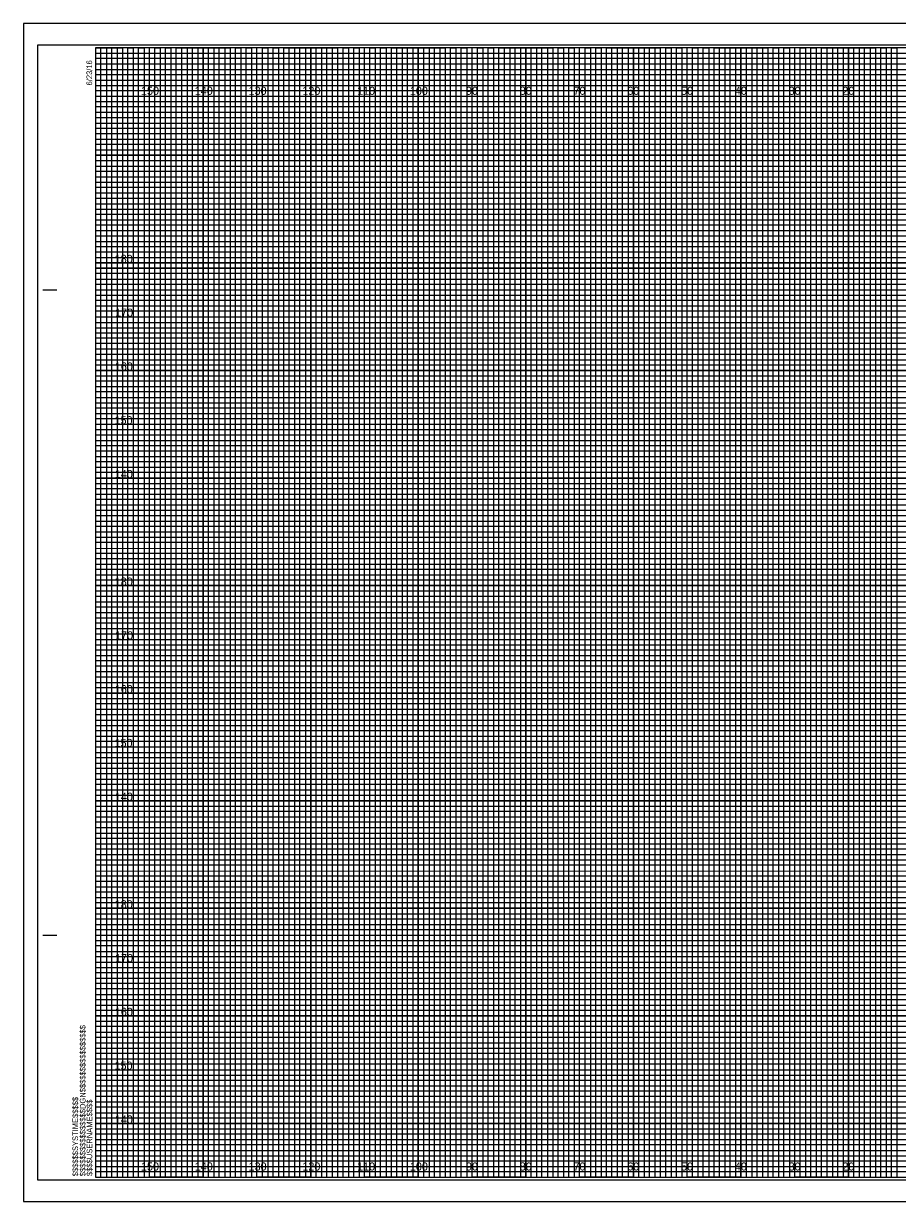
# Model space of a CAD drawing. Extents: x -13 to 323, y -5 to 4834.
# Drawn here: x -13.4 to 149.1, y 435.5 to 654.5 of the extents above; entities that cross this region are included whole.
import ezdxf

# ---------------------------------------------------------------- set-up
doc = ezdxf.new("R2010")
doc.units = 0
for name, color, linetype in [('Exist Cross Section Cell', 7, 'Continuous'), ('Exist XS Center Line Elevation Label', 7, 'Continuous'), ('Exist XS Ground Line', 7, 'Continuous'), ('Prop CMT Pvmt Course 1', 7, 'Continuous'), ('Prop CMT Pvmt Course 2', 7, 'Continuous'), ('Prop CMT Pvmt Course 3', 7, 'Continuous'), ('Prop CMT Pvmt Surface Shoulder', 7, 'Continuous'), ('Prop CMT Shld Paved Course 1', 7, 'Continuous'), ('Prop CMT Shld Paved Course 2', 7, 'Continuous'), ('Prop CMT Shld Paved Course 3', 7, 'Continuous'), ('Prop CMT Slope Grass', 7, 'Continuous')]:
    doc.layers.add(name, color=color, linetype=linetype)

msp = doc.modelspace()

# ---------------------------------------------------------------- linework, layer by layer
at = {"layer": 'Exist XS Center Line Elevation Label'}
for points in [[(0, 650), (5, 650), (5, 440), (15, 440), (15, 650), (25, 650), (25, 440), (35, 440), (35, 650), (45, 650), (45, 440), (55, 440), (55, 650), (65, 650), (65, 440), (75, 440), (75, 650), (85, 650), (85, 440), (95, 440), (95, 650), (105, 650), (105, 440), (115, 440), (115, 650), (125, 650), (125, 440), (135, 440), (135, 650), (145, 650), (145, 440), (155, 440)], [(0, 645), (275, 645)], [(0, 625), (320, 625), (320, 635), (0, 635)], [(0, 605), (320, 605), (320, 615), (0, 615)], [(0, 585), (320, 585), (320, 595), (0, 595)], [(0, 565), (320, 565), (320, 575), (0, 575)], [(0, 545), (320, 545), (320, 555), (0, 555)], [(0, 525), (320, 525), (320, 535), (0, 535)], [(0, 505), (320, 505), (320, 515), (0, 515)], [(0, 485), (320, 485), (320, 495), (0, 495)], [(0, 465), (320, 465), (320, 475), (0, 475)], [(0, 445), (320, 445), (320, 455), (0, 455)]]:
    msp.add_lwpolyline(points, dxfattribs=at)
at = {"layer": 'Exist XS Ground Line'}
for p, q in [((10, 650), (0, 650)), ((10, 440), (10, 650)), ((30, 650), (20, 650)), ((20, 650), (20, 440)), ((30, 440), (30, 650)), ((50, 650), (40, 650)), ((40, 650), (40, 440)), ((50, 440), (50, 650)), ((70, 650), (60, 650)), ((60, 650), (60, 440)), ((70, 440), (70, 650)), ((90, 650), (80, 650)), ((80, 650), (80, 440)), ((90, 440), (90, 650)), ((110, 650), (100, 650)), ((100, 650), (100, 440)), ((110, 440), (110, 650)), ((130, 650), (120, 650)), ((120, 650), (120, 440)), ((130, 440), (130, 650)), ((150, 650), (140, 650)), ((140, 650), (140, 440)), ((20, 440), (10, 440)), ((40, 440), (30, 440)), ((60, 440), (50, 440)), ((80, 440), (70, 440)), ((100, 440), (90, 440)), ((120, 440), (110, 440)), ((140, 440), (130, 440))]:
    msp.add_line(p, q, dxfattribs=at)
for points in [[(0, 640), (320, 640), (320, 630), (0, 630)], [(0, 620), (320, 620), (320, 610), (0, 610)], [(0, 600), (320, 600), (320, 590), (0, 590)], [(0, 580), (320, 580), (320, 570), (0, 570)], [(0, 560), (320, 560), (320, 550), (0, 550)], [(0, 540), (320, 540), (320, 530), (0, 530)], [(0, 520), (320, 520), (320, 510), (0, 510)], [(0, 500), (320, 500), (320, 490), (0, 490)], [(0, 480), (320, 480), (320, 470), (0, 470)], [(0, 460), (320, 460), (320, 450), (0, 450)]]:
    msp.add_lwpolyline(points, dxfattribs=at)
at = {"layer": 'Prop CMT Pvmt Course 1'}
for points in [[(0, 440), (1, 440), (1, 650), (2, 650), (2, 440)], [(2, 440), (3, 440), (3, 650), (4, 650), (4, 440)], [(5, 440), (6, 440), (6, 650), (7, 650), (7, 440)], [(7, 440), (8, 440), (8, 650), (9, 650), (9, 440)], [(10, 440), (11, 440), (11, 650), (12, 650), (12, 440)], [(12, 440), (13, 440), (13, 650), (14, 650), (14, 440)], [(15, 440), (16, 440), (16, 650), (17, 650), (17, 440)], [(17, 440), (18, 440), (18, 650), (19, 650), (19, 440)], [(20, 440), (21, 440), (21, 650), (22, 650), (22, 440)], [(22, 440), (23, 440), (23, 650), (24, 650), (24, 440)], [(25, 440), (26, 440), (26, 650), (27, 650), (27, 440)], [(27, 440), (28, 440), (28, 650), (29, 650), (29, 440)], [(30, 440), (31, 440), (31, 650), (32, 650), (32, 440)], [(32, 440), (33, 440), (33, 650), (34, 650), (34, 440)], [(35, 440), (36, 440), (36, 650), (37, 650), (37, 440)], [(37, 440), (38, 440), (38, 650), (39, 650), (39, 440)], [(40, 440), (41, 440), (41, 650), (42, 650), (42, 440)], [(42, 440), (43, 440), (43, 650), (44, 650), (44, 440)], [(45, 440), (46, 440), (46, 650), (47, 650), (47, 440)], [(47, 440), (48, 440), (48, 650), (49, 650), (49, 440)], [(50, 440), (51, 440), (51, 650), (52, 650), (52, 440)], [(52, 440), (53, 440), (53, 650), (54, 650), (54, 440)], [(55, 440), (56, 440), (56, 650), (57, 650), (57, 440)], [(57, 440), (58, 440), (58, 650), (59, 650), (59, 440)], [(60, 440), (61, 440), (61, 650), (62, 650), (62, 440)], [(62, 440), (63, 440), (63, 650), (64, 650), (64, 440)], [(65, 440), (66, 440), (66, 650), (67, 650), (67, 440)], [(67, 440), (68, 440), (68, 650), (69, 650), (69, 440)], [(70, 440), (71, 440), (71, 650), (72, 650), (72, 440)], [(72, 440), (73, 440), (73, 650), (74, 650), (74, 440)], [(75, 440), (76, 440), (76, 650), (77, 650), (77, 440)], [(77, 440), (78, 440), (78, 650), (79, 650), (79, 440)], [(80, 440), (81, 440), (81, 650), (82, 650), (82, 440)], [(82, 440), (83, 440), (83, 650), (84, 650), (84, 440)], [(85, 440), (86, 440), (86, 650), (87, 650), (87, 440)], [(87, 440), (88, 440), (88, 650), (89, 650), (89, 440)], [(90, 440), (91, 440), (91, 650), (92, 650), (92, 440)], [(92, 440), (93, 440), (93, 650), (94, 650), (94, 440)], [(95, 440), (96, 440), (96, 650), (97, 650), (97, 440)], [(97, 440), (98, 440), (98, 650), (99, 650), (99, 440)], [(100, 440), (101, 440), (101, 650), (102, 650), (102, 440)], [(102, 440), (103, 440), (103, 650), (104, 650), (104, 440)], [(105, 440), (106, 440), (106, 650), (107, 650), (107, 440)], [(107, 440), (108, 440), (108, 650), (109, 650), (109, 440)], [(110, 440), (111, 440), (111, 650), (112, 650), (112, 440)], [(112, 440), (113, 440), (113, 650), (114, 650), (114, 440)], [(115, 440), (116, 440), (116, 650), (117, 650), (117, 440)], [(117, 440), (118, 440), (118, 650), (119, 650), (119, 440)], [(120, 440), (121, 440), (121, 650), (122, 650), (122, 440)], [(122, 440), (123, 440), (123, 650), (124, 650), (124, 440)], [(125, 440), (126, 440), (126, 650), (127, 650), (127, 440)], [(127, 440), (128, 440), (128, 650), (129, 650), (129, 440)], [(130, 440), (131, 440), (131, 650), (132, 650), (132, 440)], [(132, 440), (133, 440), (133, 650), (134, 650), (134, 440)], [(135, 440), (136, 440), (136, 650), (137, 650), (137, 440)], [(137, 440), (138, 440), (138, 650), (139, 650), (139, 440)], [(140, 440), (141, 440), (141, 650), (142, 650), (142, 440)], [(142, 440), (143, 440), (143, 650), (144, 650), (144, 440)], [(145, 440), (146, 440), (146, 650), (147, 650), (147, 440)], [(147, 440), (148, 440), (148, 650), (149, 650), (149, 440)]]:
    msp.add_lwpolyline(points, dxfattribs=at)
at = {"layer": 'Prop CMT Pvmt Course 2'}
for p, q in [((323.3, 654.5), (-13.4, 654.5)), ((-13.4, 654.5), (-13.4, 435.5)), ((-13.4, 435.5), (323.3, 435.5))]:
    msp.add_line(p, q, dxfattribs=at)
at = {"layer": 'Prop CMT Pvmt Surface Shoulder'}
for p, q in [((-9.8, 605), (-7.3, 605)), ((-9.7, 605), (-7.2, 605)), ((-9.8, 485), (-7.3, 485)), ((-9.7, 485), (-7.2, 485)), ((0, 440), (0, 440)), ((0, 440), (0, 440)), ((0, 440), (0, 440)), ((0, 440), (0, 440)), ((0, 440), (0, 440)), ((0, 440), (0, 440)), ((0, 440), (0, 440))]:
    msp.add_line(p, q, dxfattribs=at)
msp.add_lwpolyline([(320, 650), (0, 650), (0, 440), (320, 440)], close=True, dxfattribs=at)
at = {"layer": 'Prop CMT Shld Paved Course 1'}
msp.add_lwpolyline([(-13.4, 435.5), (323.3, 435.5), (323.3, 654.5), (-13.4, 654.5)], close=True, dxfattribs=at)
at = {"layer": 'Prop CMT Shld Paved Course 2'}
msp.add_lwpolyline([(-10.8, 439.5), (322.4, 439.5), (322.4, 650.5), (-10.8, 650.5)], close=True, dxfattribs=at)
at = {"layer": 'Prop CMT Shld Paved Course 3'}
for p, q in [((10, 440), (10, 650)), ((20, 440), (20, 650)), ((30, 440), (30, 650)), ((40, 440), (40, 650)), ((50, 440), (50, 650)), ((60, 440), (60, 650)), ((70, 440), (70, 650)), ((80, 440), (80, 650)), ((90, 440), (90, 650)), ((100, 440), (100, 650)), ((110, 440), (110, 650)), ((120, 440), (120, 650)), ((130, 440), (130, 650)), ((140, 440), (140, 650)), ((0, 640), (320, 640)), ((0, 630), (320, 630)), ((0, 620), (320, 620)), ((0, 610), (320, 610)), ((0, 600), (320, 600)), ((0, 590), (320, 590)), ((0, 580), (320, 580)), ((0, 570), (320, 570)), ((0, 560), (320, 560)), ((0, 550), (320, 550)), ((0, 540), (320, 540)), ((0, 530), (320, 530)), ((0, 520), (320, 520)), ((0, 510), (320, 510)), ((0, 500), (320, 500)), ((0, 490), (320, 490)), ((0, 480), (320, 480)), ((0, 470), (320, 470)), ((0, 460), (320, 460)), ((0, 450), (320, 450))]:
    msp.add_line(p, q, dxfattribs=at)
at = {"layer": 'Prop CMT Slope Grass'}
for p, q in [((0, 649), (260, 649)), ((260, 647.98), (0, 647.98)), ((0, 647.98), (0, 647)), ((0, 647), (260, 647)), ((260, 645.89), (0, 645.89)), ((0, 645.89), (0, 644)), ((0, 644), (320, 644))]:
    msp.add_line(p, q, dxfattribs=at)
for points in [[(0, 643), (270, 643), (320, 643), (320, 642), (0, 642)], [(0, 641), (320, 641), (320, 639), (0, 639)], [(0, 638), (320, 638), (320, 637), (0, 636.98)], [(0, 636), (320, 636), (320, 634), (0, 634)], [(0, 633), (320, 633), (320, 632), (0, 632)], [(0, 631), (320, 631), (320, 629), (0, 629)], [(0, 628), (320, 628), (320, 627), (0, 627)], [(0, 626), (320, 626), (320, 624), (0, 624)], [(0, 623), (320, 623), (320, 622), (0, 622)], [(0, 621), (320, 621), (320, 619), (0, 619)], [(0, 618), (320, 618), (320, 617), (0, 617)], [(0, 616), (320, 616), (320, 613.95), (320, 613), (320, 612), (0, 612)], [(0, 614), (320, 614), (320, 613), (0, 613)], [(0, 611), (320, 611), (320, 609), (0, 609.03)], [(0, 609.03), (320, 609), (320, 608), (0, 608)], [(0, 607), (320, 607), (320, 606), (0, 606)], [(0, 604), (320, 604), (320, 603), (0, 603)], [(0, 602), (320, 602), (320, 601), (0, 601)], [(-0.07, 598.89), (320, 598.89), (320, 597.88), (-0.07, 597.88)], [(0, 597), (320, 597), (320, 596), (0, 596)], [(0, 594), (320, 594), (320, 593), (0, 593)], [(0, 592), (320, 592), (320, 591), (0, 591)], [(0, 589), (320, 589), (320, 588), (0, 588)], [(0, 587), (320, 587), (320, 586), (0, 586)], [(0, 584), (320, 584), (320, 583), (0, 583)], [(0, 582), (320, 582), (320, 581), (0, 581)], [(0, 579), (320, 579), (319.99, 577.98), (0, 578)], [(0, 577), (320, 577), (320, 576), (0, 576)], [(0, 574), (320, 574), (320, 573), (0, 573)], [(0, 572), (320, 572), (320, 571), (0, 571)], [(0, 569), (320, 569), (320, 568), (0, 568)], [(0, 567), (320, 567), (320, 566), (0, 566)], [(0, 564), (320, 564), (320, 563), (0, 563)], [(0, 562), (320, 562), (320, 561), (0, 561)], [(0, 559), (320, 559), (320, 558), (0, 558)], [(0, 556.99), (320.07, 556.91), (320, 556), (0, 556)], [(0, 554), (320, 554), (320, 553), (0, 553)], [(0, 552), (320, 552), (320, 551), (0, 551)], [(0, 549), (320, 549), (320, 548), (0, 548)], [(0, 547), (320, 547), (320, 546), (0, 546)], [(0, 544), (320, 544), (320, 543), (0, 543)], [(0, 542), (320, 542), (320, 541), (0, 541)], [(0, 539), (320, 539), (320, 538), (0, 538)], [(0, 537), (320, 537), (320, 536), (0, 536)], [(0, 534), (320, 534), (320, 533), (0, 533)], [(0, 532), (320, 532), (320, 531), (0, 531)], [(0, 529), (320, 529), (320, 528), (0, 528)], [(0, 527), (320, 527), (320, 526), (0, 526)], [(0, 524), (320, 524), (320, 523), (0, 523)], [(0, 522), (320, 522), (320, 521), (0, 521)], [(0, 519), (320, 519), (319.99, 517.98), (0, 518)], [(0, 517), (320, 517), (320, 516), (0, 516)], [(0, 514), (320, 514), (320, 513), (0, 513)], [(0, 512), (320, 512), (320, 511), (0, 511)], [(0, 509), (320, 509), (320, 508), (0, 508)], [(0, 507), (320, 507), (320, 506), (0, 506)], [(0, 504), (320, 504), (320, 503), (0, 503)], [(0, 502), (320, 502), (320, 501), (0, 501)], [(0, 499), (320, 499), (320, 498), (0, 498)], [(0, 496.99), (320.07, 496.91), (320, 496), (0, 496)], [(0, 494), (320, 494), (320, 493), (0, 493)], [(0, 492), (320, 492), (320, 491), (0, 491)], [(0, 489), (320, 489), (320, 488), (0, 488)], [(0, 487), (320, 487), (320, 486), (0, 486)], [(0, 484), (320, 484), (320, 483), (0, 483)], [(0, 482), (320, 482), (320, 481), (0, 481)], [(0, 479), (320, 479), (320, 478), (0, 478)], [(0, 477), (320, 477), (320, 476), (0, 476)], [(0, 474), (320, 474), (320, 473), (0, 473)], [(0, 472), (320, 472), (320, 471), (0, 471)], [(0, 469), (320, 469), (320, 468), (0, 468)], [(0, 467), (320, 467), (320, 466), (0, 466)], [(0, 464), (320, 464), (320, 463), (0, 463)], [(0, 462), (320, 462), (320, 461), (0, 461)], [(0, 459), (320, 459), (320, 458), (0, 458)], [(0, 457), (320, 457), (320, 456), (0, 456)], [(0, 454), (320, 454), (320, 453), (0, 453)], [(0, 452), (320, 452), (320, 451), (0, 451)], [(0, 449), (320, 449), (320, 448), (0, 448)], [(0, 447), (320, 447), (320, 446), (0, 446)], [(0, 444), (320, 444), (320, 443), (0, 443)], [(0, 442), (320, 442), (320, 441), (0, 441)]]:
    msp.add_lwpolyline(points, dxfattribs=at)

# ---------------------------------------------------------------- texts
at = {"layer": 'Exist Cross Section Cell'}
for s, p in [('150', (8.44, 641.25)), ('140', (18.44, 641.25)), ('130', (28.44, 641.25)), ('120', (38.44, 641.25)), ('110', (48.62, 641.25)), ('100', (58.44, 641.25)), ('90', (68.86, 641.25)), ('80', (78.86, 641.25)), ('70', (88.86, 641.25)), ('60', (98.86, 641.25)), ('50', (108.86, 641.25)), ('40', (118.86, 641.25)), ('30', (128.86, 641.25)), ('20', (138.86, 641.25)), ('150', (8.44, 441.25)), ('140', (18.44, 441.25)), ('130', (28.44, 441.25)), ('120', (38.44, 441.25)), ('110', (48.62, 441.25)), ('100', (58.44, 441.25)), ('90', (68.86, 441.25)), ('80', (78.86, 441.25)), ('70', (88.86, 441.25)), ('60', (98.86, 441.25)), ('50', (108.86, 441.25)), ('40', (118.86, 441.25)), ('30', (128.86, 441.25)), ('20', (138.86, 441.25))]:
    msp.add_text(s, height=1.5, dxfattribs=at).set_placement(p)
at = {"layer": 'Prop CMT Pvmt Course 3'}
for s, p in [('180', (3.55, 610)), ('170', (3.61, 600)), ('160', (3.57, 590)), ('150', (3.52, 580)), ('140', (3.57, 570)), ('180', (3.55, 550)), ('170', (3.61, 540)), ('160', (3.57, 530)), ('150', (3.52, 520)), ('140', (3.57, 510)), ('180', (3.55, 490)), ('170', (3.61, 480)), ('160', (3.57, 470)), ('150', (3.52, 460)), ('140', (3.57, 450))]:
    msp.add_text(s, height=1.5, dxfattribs=at).set_placement(p)
at = {"layer": 'Prop CMT Pvmt Surface Shoulder'}
for s, p in [('6/23/16', (-0.65, 643)), ('$$$$$$$$$$$$$$$$DGN$$$$$$$$$$$$$$$$', (-1.88, 440.18)), ('$$$$$$SYSTIME$$$$$', (-3.26, 440.18)), ('$$$$USERNAME$$$$', (-0.62, 440.23))]:
    msp.add_text(s, height=1.05, rotation=90, dxfattribs=at).set_placement(p)

doc.saveas('drawing.dxf')
